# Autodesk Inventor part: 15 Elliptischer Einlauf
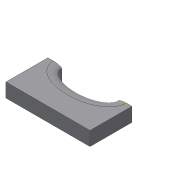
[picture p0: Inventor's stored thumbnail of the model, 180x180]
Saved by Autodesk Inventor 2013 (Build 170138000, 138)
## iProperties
Created: 2012-10
Part Number: 15 Elliptischer Einlauf
Material: Allgemein
Document SubType Name: Modeling
Designer: Administrator
Density: 1 g/cm^3
Author: Administrator
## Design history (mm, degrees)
sketch "Skizze1"
  geometry: L1 (-15, -15)-(15, -15); L2 (15, -15)-(15, 15); L3 (15, 15)-(-15, 15); L4 (-15, 15)-(-15, -15); L5 (-15, -15)-(15, 15); L6 (15, -15)-(-15, 15); 1 further point
  constraints: 12 end point, 2 midpoint, 2 parallel, 1 horizontal, 1 perpendicular
  dimensions: "d0" = 30 distance of L3.end L2.end; "d1" = 30 distance of L2.end L1.end
extrude "Extrusion1" new body sketch "Skizze1" distance "d2" = 5; taper "d3" = 0 deg
sketch "Skizze2" dims "d4" = 5, "d6" = 10
  geometry: L1 (-15, -15)-(15, -15) reference; 2 further points; 1 other entity
  constraints: 1 coincident, 1 horizontal, 2 other
extrude "Extrusion2" cut sketch "Skizze2" stored distance "d7" = 5; taper "d8" = 0 deg
chamfer "Fase1" distance "d9" = 3; stored, may be unused: second distance "d10" = 1, angle "d11" = 45 deg
feature "Fläche löschen1"
workpoint "Arbeitspunkt1"
workpoint "Arbeitspunkt2"
feature "Fläche heften2"
node "Volumenkörper1"
sketch "Skizze4"
  geometry: L1 (-10, 4)-(-13, 4); L2 (-13, 4)-(-13, 5); 2 further points; 1 other entity
  constraints: 4 end point, 2 horizontal, 1 coincident, 1 perpendicular, 4 other
sketch "3D-Skizze1"
node "Fläche2"
feature "Sweeping-Fläche1" dims "d16" = 0
